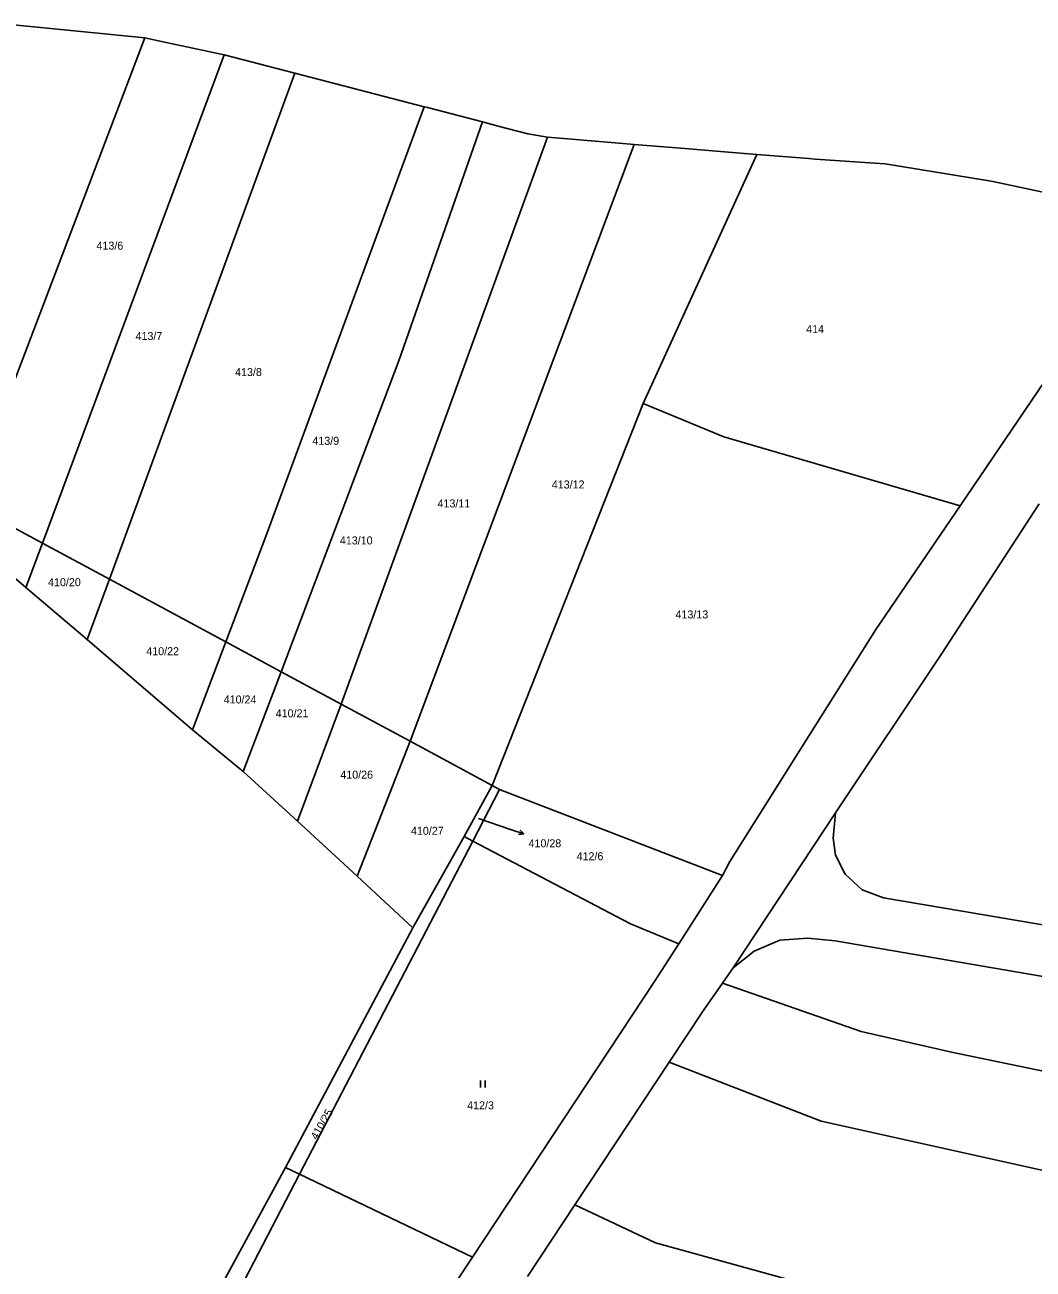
# Model space of a CAD drawing. Extents: x -744566 to -741843, y -1128407 to -1126744.
# Drawn here: x -743655.8 to -743441.6, y -1127120.7 to -1126856.5 of the extents above; entities that cross this region are included whole.
import ezdxf

# ---------------------------------------------------------------- set-up
doc = ezdxf.new("R2010")
doc.units = 0
for name, color, linetype in [('Hranice parcel', 7, 'Continuous'), ('Parcelní čísla', 7, 'Continuous'), ('Pop  PČ popisy', 7, 'Continuous'), ('Značky kultur', 7, 'Continuous')]:
    doc.layers.add(name, color=color, linetype=linetype)

msp = doc.modelspace()

# ---------------------------------------------------------------- linework, layer by layer
at = {"layer": 'Hranice parcel'}
for p, q in [((-743667.9, -1126958), (-743630.32, -1126859.26)), ((-743652.05, -1126966.54), (-743613.43, -1126862.82)), ((-743613.43, -1126862.82), (-743598.46, -1126866.7)), ((-743637.84, -1126974.2), (-743598.46, -1126866.7)), ((-743598.46, -1126866.7), (-743570.98, -1126873.86)), ((-743558.58, -1126877.09), (-743555.26, -1126877.96)), ((-743555.26, -1126877.96), (-743548.99, -1126879.59)), ((-743588.59, -1127000.75), (-743544.8, -1126880.33)), ((-743548.99, -1126879.59), (-743544.8, -1126880.33)), ((-743573.98, -1127008.62), (-743526.35, -1126881.85)), ((-743524.49, -1126936.89), (-743500.35, -1126883.98)), ((-743556.57, -1127018), (-743524.49, -1126936.89)), ((-743652.05, -1126966.54), (-743667.9, -1126958)), ((-743670.03, -1126963.61), (-743655.57, -1126975.98)), ((-743655.57, -1126975.98), (-743652.05, -1126966.54)), ((-743637.84, -1126974.2), (-743652.05, -1126966.54)), ((-743642.55, -1126987.04), (-743655.57, -1126975.98)), ((-743642.55, -1126987.04), (-743637.84, -1126974.2)), ((-743613.12, -1126987.52), (-743637.84, -1126974.2)), ((-743620.19, -1127006.18), (-743642.55, -1126987.04)), ((-743620.19, -1127006.18), (-743613.12, -1126987.52)), ((-743601.38, -1126993.85), (-743613.12, -1126987.52)), ((-743601.38, -1126993.85), (-743609.42, -1127015.07)), ((-743588.59, -1127000.75), (-743601.38, -1126993.85)), ((-743597.86, -1127025.57), (-743588.59, -1127000.75)), ((-743573.98, -1127008.62), (-743588.59, -1127000.75)), ((-743609.42, -1127015.07), (-743620.19, -1127006.18)), ((-743585.23, -1127037.3), (-743573.98, -1127008.62)), ((-743556.57, -1127018), (-743573.98, -1127008.62)), ((-743597.86, -1127025.57), (-743609.42, -1127015.07)), ((-743562.48, -1127028.88), (-743556.57, -1127018)), ((-743554.98, -1127018.86), (-743556.57, -1127018)), ((-743560.68, -1127029.82), (-743554.98, -1127018.86)), ((-743507.61, -1127037.13), (-743554.98, -1127018.86)), ((-743585.23, -1127037.3), (-743597.86, -1127025.57)), ((-743483.62, -1127023.79), (-743505.37, -1127056.75)), ((-743562.48, -1127028.88), (-743573.39, -1127048.24)), ((-743560.68, -1127029.82), (-743562.48, -1127028.88)), ((-743560.68, -1127029.82), (-743597.45, -1127100.54)), ((-743573.39, -1127048.24), (-743585.23, -1127037.3)), ((-743507.61, -1127037.13), (-743516.89, -1127051.64)), ((-743600.41, -1127099.12), (-743573.39, -1127048.24)), ((-743507.61, -1127059.97), (-743505.37, -1127056.75)), ((-743538.97, -1127107.07), (-743518.91, -1127076.75)), ((-743646.48, -1127183.8), (-743600.41, -1127099.12)), ((-743597.45, -1127100.54), (-743600.41, -1127099.12)), ((-743642.12, -1127186.45), (-743597.45, -1127100.54)), ((-743597.45, -1127100.54), (-743560.72, -1127118.19)), ((-743549.04, -1127122.29), (-743538.97, -1127107.07))]:
    msp.add_line(p, q, dxfattribs=at)
for points in [[(-743670.72, -1126857.13), (-743670.09, -1126857.07), (-743658.2, -1126856.48), (-743630.32, -1126859.26)], [(-743630.32, -1126859.26), (-743626.75, -1126860), (-743613.43, -1126862.82)], [(-743613.12, -1126987.52), (-743604.54, -1126964.89), (-743570.98, -1126873.86)], [(-743570.98, -1126873.86), (-743570.28, -1126874.05), (-743558.58, -1126877.09)], [(-743601.38, -1126993.85), (-743576.26, -1126927.6), (-743558.58, -1126877.09)], [(-743544.8, -1126880.33), (-743529.54, -1126881.59), (-743526.35, -1126881.85)], [(-743526.35, -1126881.85), (-743516.49, -1126882.66), (-743504.64, -1126883.63), (-743500.35, -1126883.98)], [(-743500.35, -1126883.98), (-743489.25, -1126884.88), (-743487.94, -1126884.99), (-743474.2, -1126885.91), (-743473.08, -1126885.98), (-743451, -1126889.6), (-743449.81, -1126889.8), (-743427.91, -1126894.47), (-743417.33, -1126896.72)], [(-743417.33, -1126896.72), (-743424.78, -1126909.13), (-743439.2, -1126932.19), (-743457.17, -1126958.62)], [(-743457.17, -1126958.62), (-743507.35, -1126943.98), (-743524.49, -1126936.89)], [(-743457.17, -1126958.62), (-743475.03, -1126984.89), (-743506.07, -1127034.13), (-743507.61, -1127037.13)], [(-743440.35, -1126958.18), (-743461.19, -1126990.18), (-743483.62, -1127023.79)], [(-743483.62, -1127023.79), (-743484.09, -1127029.22), (-743483.64, -1127032.8), (-743481.55, -1127036.83), (-743477.98, -1127040.17), (-743473.44, -1127041.87), (-743424.12, -1127050.25)], [(-743516.89, -1127051.64), (-743527.15, -1127047.39), (-743560.68, -1127029.82)], [(-743560.72, -1127118.19), (-743522.03, -1127059.68), (-743516.89, -1127051.64)], [(-743505.37, -1127056.75), (-743500.91, -1127053.2), (-743495.43, -1127050.9), (-743489.52, -1127050.44), (-743483.7, -1127051.01), (-743385.04, -1127067.93), (-743311.47, -1127080.65)], [(-743518.91, -1127076.75), (-743511.71, -1127065.87), (-743507.61, -1127059.97)], [(-743315.45, -1127100.94), (-743412.49, -1127084.27), (-743458.97, -1127074.63), (-743478.13, -1127070.26), (-743507.61, -1127059.97)], [(-743320.04, -1127120.06), (-743373.57, -1127111.3), (-743433.39, -1127101.15), (-743486.65, -1127089.31), (-743518.91, -1127076.75)], [(-743227.63, -1127169.97), (-743272.53, -1127161.95), (-743339.46, -1127150.28), (-743422.36, -1127136.74), (-743485.93, -1127125.07), (-743521.87, -1127115.17), (-743538.97, -1127107.07)], [(-743560.72, -1127118.19), (-743576.94, -1127142.72), (-743616.38, -1127202.08)]]:
    msp.add_lwpolyline(points, dxfattribs=at)
at = {"layer": 'Pop  PČ popisy'}
for p, q in [((-743559.41, -1127025), (-743552.66, -1127027.33)), ((-743552.66, -1127027.33), (-743549.823, -1127028.307)), ((-743549.823, -1127028.307), (-743550.932, -1127028.454)), ((-743549.823, -1127028.307), (-743550.606, -1127027.508))]:
    msp.add_line(p, q, dxfattribs=at)
at = {"layer": 'Značky kultur'}
for p, q in [((-743559.001, -1127082.18), (-743559.001, -1127080.68)), ((-743558, -1127082.18), (-743558, -1127080.68))]:
    msp.add_line(p, q, dxfattribs=at)

# ---------------------------------------------------------------- texts
at = {"layer": 'Parcelní čísla'}
for s, p in [('413/6', (-743640.58, -1126904.21)), ('414', (-743489.84, -1126921.93)), ('413/7', (-743632.29, -1126923.41)), ('413/8', (-743611.14, -1126931.06)), ('413/9', (-743594.73, -1126945.66)), ('413/12', (-743543.87, -1126954.94)), ('413/11', (-743568.15, -1126958.96)), ('413/10', (-743588.89, -1126966.82)), ('410/20', (-743650.87, -1126975.69)), ('413/13', (-743517.6, -1126982.54)), ('410/22', (-743630.01, -1126990.35)), ('410/24', (-743613.57, -1127000.6)), ('410/21', (-743602.51, -1127003.54)), ('410/26', (-743588.8, -1127016.57)), ('410/27', (-743573.79, -1127028.49)), ('410/28', (-743548.82, -1127031.143)), ('412/6', (-743538.61, -1127033.89)), ('412/3', (-743561.86, -1127086.8))]:
    msp.add_text(s, height=1.7, dxfattribs=at).set_placement(p)
msp.add_text('410/25', height=1.7, rotation=60, dxfattribs=at).set_placement((-743593.763, -1127093.395))

doc.saveas('drawing.dxf')
